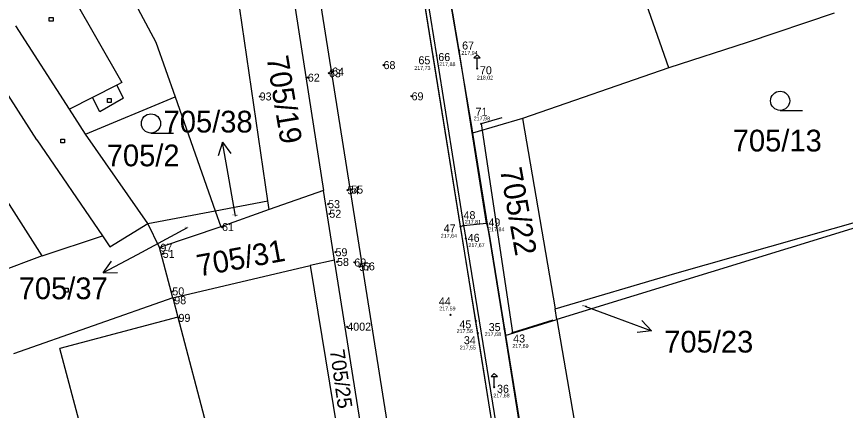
# Model space of a CAD drawing. Extents: x -711879 to -711361, y -1048782 to -1048177.
# Drawn here: x -711669.9 to -711605.1, y -1048600.7 to -1048569.9 of the extents above; entities that cross this region are included whole.
import ezdxf

# ---------------------------------------------------------------- set-up
doc = ezdxf.new("R2010")
doc.units = 0
for name, color, linetype in [('body', 7, 'Continuous'), ('kresba', 7, 'Continuous'), ('Vrstva 1', 7, 'Continuous'), ('Vrstva 13', 7, 'Continuous'), ('Vrstva 14', 7, 'Continuous'), ('Vrstva 16', 7, 'Continuous'), ('Vrstva 2', 7, 'Continuous'), ('Vrstva 20', 7, 'Continuous'), ('Vrstva 23', 7, 'Continuous'), ('Vrstva 25', 7, 'Continuous'), ('Vrstva 41', 7, 'Continuous'), ('Vrstva 46', 7, 'Continuous'), ('výšky', 7, 'Continuous')]:
    doc.layers.add(name, color=color, linetype=linetype)

msp = doc.modelspace()

# ---------------------------------------------------------------- linework, layer by layer
at = {"layer": 'kresba'}
for p, q in [((-711635.19, -1048586.31), (-711634.96, -1048586.24)), ((-711634.96, -1048586.24), (-711633.18, -1048586.06))]:
    msp.add_line(p, q, dxfattribs=at)
for points in [[(-711627.73, -1048627.29), (-711630.24, -1048616.57), (-711631.79, -1048607.69), (-711633.85, -1048594.65), (-711635.19, -1048586.31), (-711637.32, -1048573.04), (-711638.96, -1048562.71), (-711640.68, -1048551.9)], [(-711640.4, -1048551.81), (-711638.72, -1048562.7), (-711637.06, -1048572.96), (-711634.96, -1048586.24)], [(-711633.18, -1048586.06), (-711635.31, -1048572.55), (-711637.01, -1048562.39), (-711638.71, -1048551.5)], [(-711633.9, -1048573.96), (-711633.9, -1048573.14), (-711633.65, -1048573.14), (-711633.9, -1048572.89), (-711634.15, -1048573.14), (-711633.9, -1048573.14)], [(-711631.97, -1048577.81), (-711633.58, -1048578.29), (-711631.14, -1048594.6), (-711627.97, -1048593.61)], [(-711634.96, -1048586.24), (-711634.79, -1048587.25), (-711630.05, -1048616.54), (-711627.59, -1048627.26)], [(-711633.18, -1048586.06), (-711632.952, -1048586.947), (-711628.22, -1048616.182), (-711625.56, -1048626.74)], [(-711632.56, -1048598.87), (-711632.56, -1048598.05), (-711632.31, -1048598.05), (-711632.56, -1048597.8), (-711632.81, -1048598.05), (-711632.56, -1048598.05)]]:
    msp.add_lwpolyline(points, dxfattribs=at)
at = {"layer": 'Vrstva 1'}
for p, q in [((-711638.79, -1048552.06), (-711634.35, -1048578.5)), ((-711640.68, -1048552.25), (-711617.59, -1048696.39)), ((-711648.56, -1048553.71), (-711625.71, -1048697.17)), ((-711618.94, -1048573.9), (-711621.79, -1048565.72)), ((-711648.36, -1048567.63), (-711645.9, -1048583.49)), ((-711660.79, -1048568.53), (-711658.99, -1048571.9)), ((-711650.24, -1048584.31), (-711652.42, -1048569.3)), ((-711606.02, -1048569.63), (-711612.81, -1048571.92)), ((-711665.72, -1048577.15), (-711669.91, -1048570.62)), ((-711658.99, -1048571.9), (-711657.49, -1048576.18)), ((-711612.81, -1048571.92), (-711618.94, -1048573.9)), ((-711667.86, -1048588.61), (-711678.03, -1048572.83)), ((-711618.94, -1048573.9), (-711630.36, -1048577.88)), ((-711664.47, -1048579.09), (-711657.49, -1048576.18)), ((-711657.49, -1048576.18), (-711654.36, -1048585.08)), ((-711664.47, -1048579.09), (-711665.72, -1048577.15)), ((-711630.36, -1048577.88), (-711634.27, -1048579.02)), ((-711630.36, -1048577.88), (-711627.81, -1048592.75)), ((-711634.35, -1048578.5), (-711634.27, -1048579.02)), ((-711659.62, -1048586.07), (-711664.47, -1048579.09)), ((-711634.27, -1048579.02), (-711631.72, -1048594.83)), ((-711645.9, -1048583.49), (-711650.14, -1048585)), ((-711645.03, -1048588.95), (-711645.9, -1048583.49)), ((-711654.36, -1048585.08), (-711650.24, -1048584.31)), ((-711650.14, -1048585), (-711650.24, -1048584.31)), ((-711597.05, -1048584.15), (-711627.67, -1048593.58)), ((-711659.62, -1048586.07), (-711654.36, -1048585.08)), ((-711654.36, -1048585.08), (-711653.91, -1048586.35)), ((-711650.14, -1048585), (-711653.91, -1048586.35)), ((-711618.47, -1048589.99), (-711602.15, -1048585.34)), ((-711658.71, -1048587.96), (-711659.62, -1048586.07)), ((-711653.91, -1048586.35), (-711658.71, -1048587.96)), ((-711657.67, -1048591.88), (-711658.71, -1048587.96)), ((-711667.86, -1048588.61), (-711673.81, -1048590.81)), ((-711645.03, -1048588.95), (-711646.95, -1048589.37)), ((-711641.83, -1048609.02), (-711645.03, -1048588.95)), ((-711657.67, -1048591.88), (-711646.95, -1048589.37)), ((-711646.95, -1048589.37), (-711643.61, -1048609.59)), ((-711627.81, -1048592.75), (-711618.47, -1048589.99)), ((-711657.67, -1048591.88), (-711670.11, -1048596.26)), ((-711657.67, -1048591.88), (-711657.27, -1048593.41)), ((-711627.67, -1048593.58), (-711627.81, -1048592.75)), ((-711657.27, -1048593.41), (-711666.48, -1048595.85)), ((-711657.27, -1048593.41), (-711652.27, -1048612.29)), ((-711631.72, -1048594.83), (-711627.67, -1048593.58)), ((-711627.67, -1048593.58), (-711617.28, -1048654.08)), ((-711631.72, -1048594.83), (-711613.65, -1048707.15)), ((-711661.49, -1048614.73), (-711666.48, -1048595.85))]:
    msp.add_line(p, q, dxfattribs=at)
at = {"layer": 'Vrstva 13'}
for p, q in [((-711652.77, -1048585.5), (-711653.27, -1048582.67)), ((-711656.55, -1048586.43), (-711660.45, -1048588.52)), ((-711625.48, -1048592.55), (-711623.1, -1048593.43))]:
    msp.add_line(p, q, dxfattribs=at)
at = {"layer": 'Vrstva 16'}
for p, q in [((-711653.792, -1048579.715), (-711654.11, -1048580.787)), ((-711653.27, -1048582.67), (-711653.792, -1048579.715)), ((-711653.792, -1048579.715), (-711653.125, -1048580.613)), ((-711660.45, -1048588.52), (-711663.092, -1048589.94)), ((-711663.092, -1048589.94), (-711662.448, -1048589.026)), ((-711663.092, -1048589.94), (-711661.974, -1048589.907)), ((-711623.1, -1048593.43), (-711620.286, -1048594.47)), ((-711620.286, -1048594.47), (-711621.05, -1048593.654)), ((-711620.286, -1048594.47), (-711621.397, -1048594.592))]:
    msp.add_line(p, q, dxfattribs=at)
at = {"layer": 'Vrstva 2'}
for p, q in [((-711667.84, -1048564.2), (-711661.64, -1048575.07)), ((-711668.28, -1048579.53), (-711672.9, -1048572.39)), ((-711662.04, -1048575.27), (-711663.93, -1048576.24)), ((-711661.64, -1048575.07), (-711662.04, -1048575.27)), ((-711661.52, -1048576.29), (-711662.04, -1048575.27)), ((-711663.93, -1048576.24), (-711665.72, -1048577.15)), ((-711663.36, -1048577.34), (-711663.93, -1048576.24)), ((-711661.52, -1048576.29), (-711663.36, -1048577.34)), ((-711668.28, -1048579.53), (-711663.16, -1048587.05)), ((-711662.58, -1048587.91), (-711659.62, -1048586.07)), ((-711667.86, -1048588.61), (-711663.16, -1048587.05)), ((-711663.16, -1048587.05), (-711662.58, -1048587.91))]:
    msp.add_line(p, q, dxfattribs=at)
at = {"layer": 'Vrstva 20'}
for p, q in [((-711635.31, -1048572.55), (-711635.36, -1048572.5)), ((-711635.31, -1048572.55), (-711635.36, -1048572.6)), ((-711635.31, -1048572.55), (-711635.26, -1048572.5)), ((-711635.31, -1048572.55), (-711635.26, -1048572.6)), ((-711637.32, -1048573.04), (-711637.37, -1048572.99)), ((-711637.32, -1048573.04), (-711637.37, -1048573.09)), ((-711637.32, -1048573.04), (-711637.27, -1048572.99)), ((-711637.32, -1048573.04), (-711637.27, -1048573.09)), ((-711637.06, -1048572.96), (-711637.11, -1048572.91)), ((-711637.06, -1048572.96), (-711637.11, -1048573.01)), ((-711637.06, -1048572.96), (-711637.01, -1048572.91)), ((-711637.06, -1048572.96), (-711637.01, -1048573.01)), ((-711641.21, -1048573.7), (-711641.26, -1048573.65)), ((-711641.21, -1048573.7), (-711641.26, -1048573.75)), ((-711641.21, -1048573.7), (-711641.16, -1048573.65)), ((-711641.21, -1048573.7), (-711641.16, -1048573.75)), ((-711633.9, -1048573.96), (-711633.95, -1048573.91)), ((-711633.9, -1048573.96), (-711633.95, -1048574.01)), ((-711633.9, -1048573.96), (-711633.85, -1048573.91)), ((-711633.9, -1048573.96), (-711633.85, -1048574.01)), ((-711647.12, -1048574.68), (-711647.17, -1048574.63)), ((-711647.12, -1048574.68), (-711647.17, -1048574.73)), ((-711647.12, -1048574.68), (-711647.07, -1048574.63)), ((-711647.12, -1048574.68), (-711647.07, -1048574.73)), ((-711645.47, -1048574.34), (-711645.52, -1048574.29)), ((-711645.47, -1048574.34), (-711645.52, -1048574.39)), ((-711645.47, -1048574.34), (-711645.42, -1048574.29)), ((-711645.47, -1048574.34), (-711645.42, -1048574.39)), ((-711645.22, -1048574.2), (-711645.27, -1048574.15)), ((-711645.22, -1048574.2), (-711645.27, -1048574.25)), ((-711645.22, -1048574.2), (-711645.17, -1048574.15)), ((-711645.22, -1048574.2), (-711645.17, -1048574.25)), ((-711650.88, -1048576.15), (-711650.93, -1048576.1)), ((-711650.88, -1048576.15), (-711650.93, -1048576.2)), ((-711650.88, -1048576.15), (-711650.83, -1048576.1)), ((-711650.88, -1048576.15), (-711650.83, -1048576.2)), ((-711639.02, -1048576.14), (-711639.07, -1048576.09)), ((-711639.02, -1048576.14), (-711639.07, -1048576.19)), ((-711639.02, -1048576.14), (-711638.97, -1048576.09)), ((-711639.02, -1048576.14), (-711638.97, -1048576.19)), ((-711633.58, -1048578.29), (-711633.63, -1048578.24)), ((-711633.58, -1048578.29), (-711633.63, -1048578.34)), ((-711633.58, -1048578.29), (-711633.53, -1048578.24)), ((-711633.58, -1048578.29), (-711633.53, -1048578.34)), ((-711644.03, -1048583.48), (-711644.08, -1048583.43)), ((-711644.03, -1048583.48), (-711644.08, -1048583.53)), ((-711644.03, -1048583.48), (-711643.98, -1048583.43)), ((-711644.03, -1048583.48), (-711643.98, -1048583.53)), ((-711643.73, -1048583.43), (-711643.78, -1048583.38)), ((-711643.73, -1048583.43), (-711643.78, -1048583.48)), ((-711643.73, -1048583.43), (-711643.68, -1048583.38)), ((-711643.73, -1048583.43), (-711643.68, -1048583.48)), ((-711645.54, -1048584.57), (-711645.59, -1048584.52)), ((-711645.54, -1048584.57), (-711645.59, -1048584.62)), ((-711645.54, -1048584.57), (-711645.49, -1048584.52)), ((-711645.54, -1048584.57), (-711645.49, -1048584.62)), ((-711645.44, -1048585.32), (-711645.49, -1048585.27)), ((-711645.44, -1048585.32), (-711645.49, -1048585.37)), ((-711645.44, -1048585.32), (-711645.39, -1048585.27)), ((-711645.44, -1048585.32), (-711645.39, -1048585.37)), ((-711653.82, -1048586.36), (-711653.87, -1048586.31)), ((-711653.82, -1048586.36), (-711653.87, -1048586.41)), ((-711653.82, -1048586.36), (-711653.77, -1048586.31)), ((-711653.82, -1048586.36), (-711653.77, -1048586.41)), ((-711635.19, -1048586.31), (-711635.24, -1048586.26)), ((-711635.19, -1048586.31), (-711635.24, -1048586.36)), ((-711635.19, -1048586.31), (-711635.14, -1048586.26)), ((-711635.19, -1048586.31), (-711635.14, -1048586.36)), ((-711634.96, -1048586.24), (-711635.01, -1048586.19)), ((-711634.96, -1048586.24), (-711635.01, -1048586.29)), ((-711634.96, -1048586.24), (-711634.91, -1048586.19)), ((-711634.96, -1048586.24), (-711634.91, -1048586.29)), ((-711633.18, -1048586.06), (-711633.23, -1048586.01)), ((-711633.18, -1048586.06), (-711633.23, -1048586.11)), ((-711633.18, -1048586.06), (-711633.13, -1048586.01)), ((-711633.18, -1048586.06), (-711633.13, -1048586.11)), ((-711634.79, -1048587.25), (-711634.84, -1048587.2)), ((-711634.79, -1048587.25), (-711634.84, -1048587.3)), ((-711634.79, -1048587.25), (-711634.74, -1048587.2)), ((-711634.79, -1048587.25), (-711634.74, -1048587.3)), ((-711658.63, -1048587.98), (-711658.68, -1048587.93)), ((-711658.63, -1048587.98), (-711658.68, -1048588.03)), ((-711658.63, -1048587.98), (-711658.58, -1048587.93)), ((-711658.63, -1048587.98), (-711658.58, -1048588.03)), ((-711644.96, -1048588.33), (-711645.01, -1048588.28)), ((-711644.96, -1048588.33), (-711645.01, -1048588.38)), ((-711644.96, -1048588.33), (-711644.91, -1048588.28)), ((-711644.96, -1048588.33), (-711644.91, -1048588.38)), ((-711658.45, -1048588.46), (-711658.5, -1048588.41)), ((-711658.45, -1048588.46), (-711658.5, -1048588.51)), ((-711658.45, -1048588.46), (-711658.4, -1048588.41)), ((-711658.45, -1048588.46), (-711658.4, -1048588.51)), ((-711644.84, -1048589.09), (-711644.89, -1048589.04)), ((-711644.84, -1048589.09), (-711644.89, -1048589.14)), ((-711644.84, -1048589.09), (-711644.79, -1048589.04)), ((-711644.84, -1048589.09), (-711644.79, -1048589.14)), ((-711643.49, -1048589.13), (-711643.54, -1048589.08)), ((-711643.49, -1048589.13), (-711643.54, -1048589.18)), ((-711643.49, -1048589.13), (-711643.44, -1048589.08)), ((-711643.49, -1048589.13), (-711643.44, -1048589.18)), ((-711643.1, -1048589.48), (-711643.15, -1048589.43)), ((-711643.1, -1048589.48), (-711643.15, -1048589.53)), ((-711643.1, -1048589.48), (-711643.05, -1048589.43)), ((-711643.1, -1048589.48), (-711643.05, -1048589.53)), ((-711642.82, -1048589.43), (-711642.87, -1048589.38)), ((-711642.82, -1048589.43), (-711642.87, -1048589.48)), ((-711642.82, -1048589.43), (-711642.77, -1048589.38)), ((-711642.82, -1048589.43), (-711642.77, -1048589.48)), ((-711657.7, -1048591.39), (-711657.75, -1048591.34)), ((-711657.7, -1048591.39), (-711657.75, -1048591.44)), ((-711657.7, -1048591.39), (-711657.65, -1048591.34)), ((-711657.7, -1048591.39), (-711657.65, -1048591.44)), ((-711657.55, -1048592.08), (-711657.6, -1048592.03)), ((-711657.55, -1048592.08), (-711657.6, -1048592.13)), ((-711657.55, -1048592.08), (-711657.5, -1048592.03)), ((-711657.55, -1048592.08), (-711657.5, -1048592.13)), ((-711657.22, -1048593.46), (-711657.27, -1048593.41)), ((-711657.22, -1048593.46), (-711657.27, -1048593.51)), ((-711657.22, -1048593.46), (-711657.17, -1048593.41)), ((-711657.22, -1048593.46), (-711657.17, -1048593.51)), ((-711635.97, -1048593.23), (-711636.02, -1048593.18)), ((-711635.97, -1048593.23), (-711636.02, -1048593.28)), ((-711635.97, -1048593.23), (-711635.92, -1048593.18)), ((-711635.97, -1048593.23), (-711635.92, -1048593.28)), ((-711644.04, -1048594.15), (-711644.09, -1048594.1)), ((-711644.04, -1048594.15), (-711644.09, -1048594.2)), ((-711644.04, -1048594.15), (-711643.99, -1048594.1)), ((-711644.04, -1048594.15), (-711643.99, -1048594.2)), ((-711634.01, -1048593.7), (-711634.06, -1048593.65)), ((-711634.01, -1048593.7), (-711634.06, -1048593.75)), ((-711634.01, -1048593.7), (-711633.96, -1048593.65)), ((-711634.01, -1048593.7), (-711633.96, -1048593.75)), ((-711633.85, -1048594.65), (-711633.9, -1048594.6)), ((-711633.85, -1048594.65), (-711633.9, -1048594.7)), ((-711633.85, -1048594.65), (-711633.8, -1048594.6)), ((-711633.85, -1048594.65), (-711633.8, -1048594.7)), ((-711631.76, -1048594.31), (-711631.81, -1048594.26)), ((-711631.76, -1048594.31), (-711631.81, -1048594.36)), ((-711631.76, -1048594.31), (-711631.71, -1048594.26)), ((-711631.76, -1048594.31), (-711631.71, -1048594.36)), ((-711631.14, -1048594.6), (-711631.19, -1048594.55)), ((-711631.14, -1048594.6), (-711631.19, -1048594.65)), ((-711631.14, -1048594.6), (-711631.09, -1048594.55)), ((-711631.14, -1048594.6), (-711631.09, -1048594.65)), ((-711632.56, -1048598.87), (-711632.61, -1048598.82)), ((-711632.56, -1048598.87), (-711632.61, -1048598.92)), ((-711632.56, -1048598.87), (-711632.51, -1048598.82)), ((-711632.56, -1048598.87), (-711632.51, -1048598.92))]:
    msp.add_line(p, q, dxfattribs=at)
at = {"layer": 'Vrstva 23'}
for p, q in [((-711610.24, -1048577.24), (-711608.49, -1048577.24)), ((-711659.37, -1048579.01), (-711657.62, -1048579.01))]:
    msp.add_line(p, q, dxfattribs=at)
for centre in [(-711610.24, -1048576.49), (-711659.37, -1048578.26)]:
    msp.add_circle(centre, 0.75, dxfattribs=at)
at = {"layer": 'Vrstva 25'}
for p, q in [((-711667.31, -1048569.97), (-711667.01, -1048569.97)), ((-711667.31, -1048570.27), (-711667.31, -1048569.97)), ((-711667.01, -1048569.97), (-711667.01, -1048570.27)), ((-711667.01, -1048570.27), (-711667.31, -1048570.27)), ((-711662.77, -1048576.32), (-711662.47, -1048576.32)), ((-711662.77, -1048576.62), (-711662.77, -1048576.32)), ((-711662.47, -1048576.62), (-711662.77, -1048576.62)), ((-711662.47, -1048576.32), (-711662.47, -1048576.62)), ((-711666.42, -1048579.48), (-711666.12, -1048579.48)), ((-711666.42, -1048579.78), (-711666.42, -1048579.48)), ((-711666.12, -1048579.78), (-711666.42, -1048579.78)), ((-711666.12, -1048579.48), (-711666.12, -1048579.78)), ((-711666.14, -1048591.14), (-711665.84, -1048591.14)), ((-711666.14, -1048591.44), (-711666.14, -1048591.14)), ((-711665.84, -1048591.44), (-711666.14, -1048591.44)), ((-711665.84, -1048591.14), (-711665.84, -1048591.44))]:
    msp.add_line(p, q, dxfattribs=at)
at = {"layer": 'Vrstva 41'}
for p, q in [((-711635.31, -1048572.55), (-711635.31, -1048572.55)), ((-711637.32, -1048573.04), (-711637.32, -1048573.04)), ((-711637.06, -1048572.96), (-711637.06, -1048572.96)), ((-711641.21, -1048573.7), (-711641.21, -1048573.7)), ((-711633.9, -1048573.96), (-711633.9, -1048573.96)), ((-711647.12, -1048574.68), (-711647.12, -1048574.68)), ((-711645.47, -1048574.34), (-711645.47, -1048574.34)), ((-711645.22, -1048574.2), (-711645.22, -1048574.2)), ((-711650.88, -1048576.15), (-711650.88, -1048576.15)), ((-711639.02, -1048576.14), (-711639.02, -1048576.14)), ((-711633.58, -1048578.29), (-711633.58, -1048578.29)), ((-711644.03, -1048583.48), (-711644.03, -1048583.48)), ((-711643.73, -1048583.43), (-711643.73, -1048583.43)), ((-711645.54, -1048584.57), (-711645.54, -1048584.57)), ((-711645.44, -1048585.32), (-711645.44, -1048585.32)), ((-711653.82, -1048586.36), (-711653.82, -1048586.36)), ((-711635.19, -1048586.31), (-711635.19, -1048586.31)), ((-711634.96, -1048586.24), (-711634.96, -1048586.24)), ((-711633.18, -1048586.06), (-711633.18, -1048586.06)), ((-711634.79, -1048587.25), (-711634.79, -1048587.25)), ((-711658.63, -1048587.98), (-711658.63, -1048587.98)), ((-711644.96, -1048588.33), (-711644.96, -1048588.33)), ((-711658.45, -1048588.46), (-711658.45, -1048588.46)), ((-711644.84, -1048589.09), (-711644.84, -1048589.09)), ((-711643.49, -1048589.13), (-711643.49, -1048589.13)), ((-711643.1, -1048589.48), (-711643.1, -1048589.48)), ((-711642.82, -1048589.43), (-711642.82, -1048589.43)), ((-711657.7, -1048591.39), (-711657.7, -1048591.39)), ((-711657.55, -1048592.08), (-711657.55, -1048592.08)), ((-711657.22, -1048593.46), (-711657.22, -1048593.46)), ((-711635.97, -1048593.23), (-711635.97, -1048593.23)), ((-711644.04, -1048594.15), (-711644.04, -1048594.15)), ((-711634.01, -1048593.7), (-711634.01, -1048593.7)), ((-711633.85, -1048594.65), (-711633.85, -1048594.65)), ((-711631.76, -1048594.31), (-711631.76, -1048594.31)), ((-711631.14, -1048594.6), (-711631.14, -1048594.6)), ((-711632.56, -1048598.87), (-711632.56, -1048598.87))]:
    msp.add_line(p, q, dxfattribs=at)
at = {"layer": 'Vrstva 46'}
for p, q in [((-711658.99, -1048571.9), (-711658.99, -1048571.9)), ((-711661.64, -1048575.07), (-711661.64, -1048575.07)), ((-711661.52, -1048576.29), (-711661.52, -1048576.29)), ((-711657.49, -1048576.18), (-711657.49, -1048576.18)), ((-711668.28, -1048579.53), (-711668.28, -1048579.53)), ((-711645.9, -1048583.49), (-711645.9, -1048583.49)), ((-711654.36, -1048585.08), (-711654.36, -1048585.08)), ((-711650.14, -1048585), (-711650.14, -1048585)), ((-711659.62, -1048586.07), (-711659.62, -1048586.07)), ((-711653.91, -1048586.35), (-711653.91, -1048586.35)), ((-711668.25, -1048588), (-711668.25, -1048588)), ((-711658.71, -1048587.96), (-711658.71, -1048587.96)), ((-711667.86, -1048588.61), (-711667.86, -1048588.61)), ((-711657.67, -1048591.88), (-711657.67, -1048591.88)), ((-711657.27, -1048593.41), (-711657.27, -1048593.41)), ((-711664.46, -1048594.27), (-711664.46, -1048594.27))]:
    msp.add_line(p, q, dxfattribs=at)

# ---------------------------------------------------------------- texts
at = {"layer": 'body'}
for s, p in [('67', (-711635.071, -1048572.482)), ('66', (-711636.932, -1048573.384)), ('68', (-711641.21, -1048574.013)), ('65', (-711638.484, -1048573.634)), ('63', (-711645.47, -1048574.652)), ('64', (-711645.22, -1048574.513)), ('70', (-711633.68, -1048574.418)), ('62', (-711647.12, -1048574.993)), ('93', (-711650.88, -1048576.462)), ('69', (-711639.02, -1048576.452)), ('71', (-711634.024, -1048577.663)), ('54', (-711644.03, -1048583.792)), ('55', (-711643.73, -1048583.742)), ('53', (-711645.54, -1048584.883)), ('52', (-711645.44, -1048585.633)), ('48', (-711634.963, -1048585.745)), ('49', (-711633.017, -1048586.312)), ('61', (-711653.82, -1048586.673)), ('47', (-711636.511, -1048586.773)), ('46', (-711634.637, -1048587.515)), ('97', (-711658.63, -1048588.292)), ('51', (-711658.45, -1048588.772)), ('59', (-711644.96, -1048588.643)), ('58', (-711644.84, -1048589.403)), ('60', (-711643.49, -1048589.442)), ('57', (-711643.1, -1048589.792)), ('56', (-711642.82, -1048589.742)), ('50', (-711657.7, -1048591.702)), ('98', (-711657.55, -1048592.393)), ('44', (-711636.887, -1048592.48)), ('99', (-711657.22, -1048593.772)), ('4002', (-711644.04, -1048594.462)), ('45', (-711635.284, -1048594.275)), ('35', (-711632.995, -1048594.494)), ('43', (-711631.084, -1048595.385)), ('34', (-711634.933, -1048595.517)), ('36', (-711632.348, -1048599.318))]:
    msp.add_text(s, height=0.625, dxfattribs=at).set_placement(p)
at = {"layer": 'Vrstva 14'}
for s, height, rotation, p in [('705/19', 1.7, 279.36018, (-711650.35, -1048573.1)), ('705/22', 1.7, 280.21572, (-711632.125, -1048581.852)), ('705/31', 1.7, 10.40058, (-711655.628, -1048590.237)), ('705/25', 1.14, 278.02728, (-711645.405, -1048595.995))]:
    msp.add_text(s, height=height, rotation=rotation, dxfattribs=at).set_placement(p)
for s, height, p in [('705/13', 1.7, (-711613.94, -1048580.45)), ('705/2', 1.7, (-711662.822, -1048581.61)), ('705/38', 0.1, (-711653.023, -1048585.5)), ('705/37', 0.1, (-711656.807, -1048586.43)), ('705/23', 0.1, (-711625.733, -1048592.55))]:
    msp.add_text(s, height=height, dxfattribs=at).set_placement(p)
at = {"layer": 'Vrstva 16'}
for s, p in [('705/38', (-711658.382, -1048578.97)), ('705/37', (-711669.699, -1048592)), ('705/23', (-711619.29, -1048596.17))]:
    msp.add_text(s, height=1.7, dxfattribs=at).set_placement(p)
at = {"layer": 'výšky'}
for s, p in [('217,94', (-711635.13, -1048572.9)), ('217,88', (-711636.86, -1048573.78)), ('217,73', (-711638.81, -1048574.07)), ('218,02', (-711633.92, -1048574.83)), ('217,98', (-711634.17, -1048578.02)), ('217,81', (-711634.86, -1048586.1)), ('217,84', (-711633.04, -1048586.69)), ('217,64', (-711636.74, -1048587.19)), ('217,67', (-711634.58, -1048587.93)), ('217,59', (-711636.855, -1048592.876)), ('217,56', (-711635.5, -1048594.64)), ('217,68', (-711633.31, -1048594.88)), ('217,55', (-711635.26, -1048595.93)), ('217,69', (-711631.15, -1048595.81)), ('217,68', (-711632.63, -1048599.68))]:
    msp.add_text(s, height=0.3, dxfattribs=at).set_placement(p)

doc.saveas('drawing.dxf')
